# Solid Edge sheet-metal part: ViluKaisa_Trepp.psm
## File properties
Author: kaisa
Template: Iso Metric Sheet Metal.psm
Last saved by: kaisa
Revision: 8
Application: Solid Edge
Accuracy: 0.990
Material Thickness: 1.00 mm
Bend Radius: 1.00 mm
Relief Width: 1.00 mm
Relief Length: 0.00 mm
Neutral Factor: 0.330
Minimum Arc Length: 0.10 mm
Deviational Tolerance: 0.10 mm
Username: kaisa
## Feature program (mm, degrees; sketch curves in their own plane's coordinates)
base tab "unnamed BaseTab 1"
jog tab "JogTab_1"  OffsetDistance = 10 mm
jog tab "JogTab_3"  OffsetDistance = 10 mm
jog tab "JogTab_4"  OffsetDistance = 10 mm
jog tab "JogTab_5"  OffsetDistance = 10 mm
multibody boolean "unnamed MultibodyBoolean 1"
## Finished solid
Body 1: solid body, 14 faces, 36 edges, 24 vertices.
  Faces by surface: swept 10, plane 4
  Edges by curve: spline 20, line 16
Body 2: solid body, 46 faces, 132 edges, 88 vertices.
  Faces by surface: plane 27, cylinder 18, swept 1
  Edges by curve: line 94, circle 36, spline 2
Bounding box of the edges (mm; curved faces can reach further): 30.000 x 294.818 x 74.234, from (-15, -79.2038, -7.2091) to (15, 215.6146, 67.0252).
Cylindrical faces by radius (mm): R1 x9, R2 x9
Planar faces by outward normal: +x 3, +y 5, +z 6, -x 3, -y 6, -z 6, oblique 2
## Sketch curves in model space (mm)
line (4.0772, 3.8789, 1) -> (-3.3012, 3.8789, 1)
line (4.3651, 10.1864, 1) -> (-4.0271, 10.1864, 1)
line (4.703, 17.4523, 1) -> (-3.8018, 17.4523, 1)
line (5.1244, 25, 1) -> (-4.0368, 25, 1)
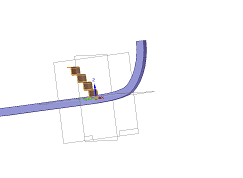
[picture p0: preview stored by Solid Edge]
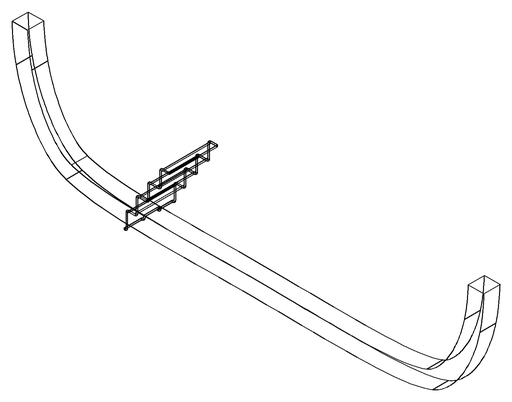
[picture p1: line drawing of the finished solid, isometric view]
